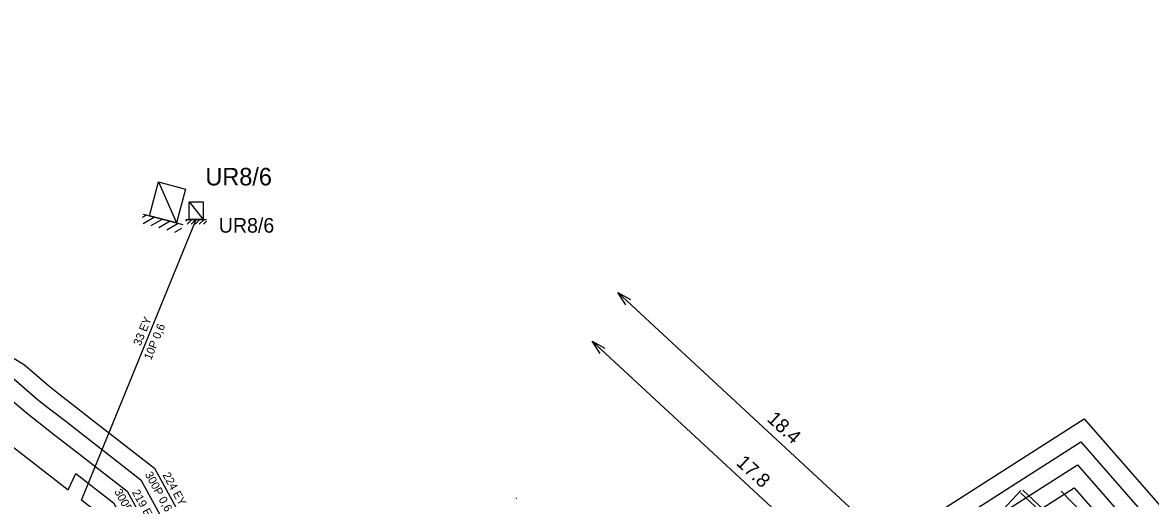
# Model space of a CAD drawing. Extents: x -756413 to -755757, y -1139003 to -1138237.
# Drawn here: x -756268.25 to -756220.06, y -1138307.56 to -1138287.22 of the extents above; entities that cross this region are included whole.
import ezdxf

# ---------------------------------------------------------------- set-up
doc = ezdxf.new("R2010")
doc.units = 0
for name, color, linetype in [('f004_rozvadec', 7, 'Continuous'), ('f004_rozvadec_ann', 7, 'Continuous'), ('f006_stp_koty', 7, 'Continuous'), ('f307_kabel_metal', 7, 'Continuous'), ('f307_kabel_metal_ann', 7, 'Continuous'), ('f307_rozvadec', 7, 'Continuous'), ('f307_rozvadec_ann', 7, 'Continuous')]:
    doc.layers.add(name, color=color, linetype=linetype)

msp = doc.modelspace()

# ---------------------------------------------------------------- linework, layer by layer
at = {"layer": 'f004_rozvadec'}
for p, q in [((-756262.446, -1138294.026), (-756261.67, -1138295.784)), ((-756262.951, -1138295.444), (-756263.134, -1138295.551)), ((-756262.612, -1138295.534), (-756263.102, -1138295.818)), ((-756263.096, -1138295.406), (-756261.404, -1138295.854)), ((-756262.274, -1138295.624), (-756262.763, -1138295.908)), ((-756261.936, -1138295.713), (-756262.425, -1138295.997)), ((-756261.598, -1138295.803), (-756262.087, -1138296.087)), ((-756261.748, -1138296.177), (-756261.443, -1138295.999))]:
    msp.add_line(p, q, dxfattribs=at)
msp.add_lwpolyline([(-756262.446, -1138294.026), (-756261.286, -1138294.334), (-756261.67, -1138295.784), (-756262.83, -1138295.476)], close=True, dxfattribs=at)
at = {"layer": 'f006_stp_koty'}
for p, q in [((-756229.33, -1138311.243), (-756242.819, -1138298.759)), ((-756230.867, -1138312.907), (-756243.91, -1138300.84)), ((-756225.6, -1138307.214), (-756230.908, -1138312.951)), ((-756225.6, -1138307.214), (-756229.371, -1138311.288)), ((-756225.515, -1138307.21), (-756224.648, -1138308.013)), ((-756220.234, -1138310.985), (-756223.877, -1138307.245)), ((-756247.153, -1138307.548), (-756247.137, -1138307.534)), ((-756225.617, -1138307.32), (-756223.892, -1138308.917))]:
    msp.add_line(p, q, dxfattribs=at)
for points in [[(-756242.48, -1138299.276), (-756242.819, -1138298.759), (-756242.276, -1138299.056)], [(-756243.571, -1138301.357), (-756243.91, -1138300.84), (-756243.367, -1138301.137)]]:
    msp.add_lwpolyline(points, dxfattribs=at)
at = {"layer": 'f307_kabel_metal'}
for points in [[(-756306.485, -1138287.215), (-756299.649, -1138292.651), (-756293.451, -1138294.434), (-756292.208, -1138293.55), (-756284.024, -1138291.942), (-756268.721, -1138301.5), (-756268.17, -1138301.844), (-756267.146, -1138302.732), (-756266.635, -1138303.13), (-756265.943, -1138303.667), (-756265.338, -1138304.142), (-756262.609, -1138306.261), (-756258.674, -1138313.461), (-756258.2, -1138314.363), (-756257.724, -1138315.263), (-756255.834, -1138321.418), (-756252.314, -1138325.16), (-756248.718, -1138323.124), (-756248.03, -1138322.735), (-756238.36, -1138317.525), (-756232.54, -1138311.52), (-756229.485, -1138308.375), (-756222.9, -1138304.16), (-756217, -1138310.915)], [(-756254.548, -1138330.753), (-756252.529, -1138329.851), (-756253.612, -1138328.339), (-756254.031, -1138327.712), (-756254.111, -1138327.627), (-756258.498, -1138322.966), (-756260.508, -1138316.415), (-756260.852, -1138315.763), (-756261.318, -1138314.88), (-756264.942, -1138308.248), (-756265.731, -1138307.633), (-756260.833, -1138295.634)], [(-756268.617, -1138302.449), (-756267.622, -1138303.312), (-756267.095, -1138303.722), (-756266.405, -1138304.258), (-756265.8, -1138304.733), (-756263.192, -1138306.758), (-756259.335, -1138313.815), (-756258.863, -1138314.713), (-756258.42, -1138315.551), (-756256.5, -1138321.805), (-756252.488, -1138326.069), (-756252.318, -1138326.024), (-756248.349, -1138323.777), (-756247.668, -1138323.392), (-756237.902, -1138318.13), (-756232.002, -1138312.042), (-756229.008, -1138308.96), (-756223.04, -1138305.14), (-756217.578, -1138311.394)], [(-756269.064, -1138303.054), (-756268.098, -1138303.892), (-756267.555, -1138304.314), (-756266.867, -1138304.849), (-756266.261, -1138305.324), (-756263.775, -1138307.255), (-756259.996, -1138314.17), (-756259.526, -1138315.063), (-756259.116, -1138315.839), (-756257.166, -1138322.192), (-756253.02, -1138326.598), (-756252.904, -1138326.72), (-756252.717, -1138326.908), (-756252.031, -1138326.723), (-756247.98, -1138324.43), (-756247.306, -1138324.049), (-756237.444, -1138318.735), (-756231.464, -1138312.564), (-756228.531, -1138309.545), (-756223.18, -1138306.12), (-756218.156, -1138311.873)], [(-756270.31, -1138304.044), (-756269.958, -1138304.264), (-756269.051, -1138305.051), (-756268.476, -1138305.498), (-756266.3, -1138307.19), (-756265.977, -1138306.494), (-756264.358, -1138307.752), (-756260.657, -1138314.525), (-756260.189, -1138315.413), (-756259.812, -1138316.127), (-756257.832, -1138322.579), (-756253.565, -1138327.113), (-756253.442, -1138327.243), (-756252.94, -1138327.745), (-756251.744, -1138327.422), (-756247.611, -1138325.083), (-756246.944, -1138324.706), (-756236.986, -1138319.34), (-756230.926, -1138313.086), (-756228.054, -1138310.13), (-756223.32, -1138307.1), (-756218.734, -1138312.352)]]:
    msp.add_lwpolyline(points, dxfattribs=at)
at = {"layer": 'f307_rozvadec'}
for p, q in [((-756261.133, -1138294.884), (-756260.533, -1138295.634)), ((-756261.27, -1138295.634), (-756260.395, -1138295.634)), ((-756261.196, -1138295.634), (-756261.27, -1138295.709)), ((-756261.02, -1138295.634), (-756261.221, -1138295.834)), ((-756260.846, -1138295.634), (-756261.046, -1138295.834)), ((-756260.671, -1138295.634), (-756260.87, -1138295.834)), ((-756260.495, -1138295.634), (-756260.696, -1138295.834)), ((-756260.52, -1138295.834), (-756260.395, -1138295.709))]:
    msp.add_line(p, q, dxfattribs=at)
msp.add_lwpolyline([(-756261.133, -1138294.884), (-756260.533, -1138294.884), (-756260.533, -1138295.634), (-756261.133, -1138295.634)], close=True, dxfattribs=at)

# ---------------------------------------------------------------- texts
at = {"layer": 'f004_rozvadec_ann'}
msp.add_text('UR8/6', height=0.75, dxfattribs=at).set_placement((-756260.437, -1138294.178))
at = {"layer": 'f006_stp_koty'}
for s, rotation, p in [('18.4', 317.22, (-756236.481, -1138304.215)), ('17.8', 317.23, (-756237.796, -1138306.088))]:
    msp.add_text(s, height=0.6, rotation=rotation, dxfattribs=at).set_placement(p)
at = {"layer": 'f307_kabel_metal_ann'}
for s, rotation, p in [('33 EY', 67.79, (-756263.21, -1138301.061)), (' 10P 0,6', 67.79, (-756262.805, -1138301.79)), (' 300P 0,6', 298.66, (-756263.098, -1138306.41)), ('224 EY', 298.66, (-756262.277, -1138306.557)), (' 300P 0,6', 298.66, (-756264.403, -1138307.148)), ('219 EY', 298.66, (-756263.582, -1138307.295))]:
    msp.add_text(s, height=0.35, rotation=rotation, dxfattribs=at).set_placement(p)
at = {"layer": 'f307_rozvadec_ann'}
msp.add_text('UR8/6', height=0.625, dxfattribs=at).set_placement((-756259.864, -1138296.198))

doc.saveas('drawing.dxf')
